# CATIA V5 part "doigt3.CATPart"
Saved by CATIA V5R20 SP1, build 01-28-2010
Part number: doigt3
Bounding box of the stored display mesh (mm): x -20 to -3, y -61.356 to 88.736, z -99.507 to -73.288
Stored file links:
  D:\thinkmotion-MPB\Dropbox\IAO_2011\MMS_GR1\0\IAO_2011_1470_mpeyrard\mpeyrard\mpeyrard\mpeyrard\IAO_2011_1470_mpeyrard\doigt3.CATPart
  D:\thinkmotion-MPB\Dropbox\IAO_2011\MMS_GR1\0\IAO_2011_1470_mpeyrard\mpeyrard\mpeyrard\mpeyrard\IAO_2011_1470_mpeyrard\mpeyrard.CATProduct
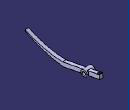
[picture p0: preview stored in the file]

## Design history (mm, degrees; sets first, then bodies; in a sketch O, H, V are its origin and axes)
External parameters (linked from other documents)
  External.Longueur_griffe = 70 mm
  External.Hauteur_griffe = 30 mm
Set1
  Line1: linked copy from another document
  Plane1: linked copy from another document
  Line2: linked copy from another document
  Line3: linked copy from another document
Body1 (main body)
  Sketch1 on yz-plane, origin (0, 0, 0), H (0, 1, 0), V (0, 0, 1)
    circle A1 centre (60, -86.6025) radius 3
    point P1 (60, -86.6025)
    circle A2 centre (60, -86.6025) radius 6
    reference projected point E1 (60, -86.6025) from Line1
    radius A2 = 6
    radius A1 = 3
    distance E1 P1 = 0
  Pad1: profile Sketch1, direction (-1, 0, 0), length 20, opposite side length -3
  Sketch2 on Plane1, origin (0, 54.6358, -87.6583), H (1, 0, 0), V (0, 0.9812, 0.1931)
    axis line L1 (-5.9206, 30.4671) -> (-26.1373, 30.4671)
    reference projected line E1 (0, 5.4671) -> (0, 30.4671) from Line2
    reference projected point E2 (0, 30.4671) from Line3
    line L2 (-13.5, 33.9671) -> (-6.5, 33.9671)
    line L3 (-6.5, 33.9671) -> (-6.5, -41.0329)
    line L4 (-6.5, -41.0329) -> (-13.5, -41.0329)
    line L5 (-13.5, -41.0329) -> (-13.5, 33.9671)
    reference projected point E3 (0, 30.4671) from Line3
    distance L1 E2 = 0
    distance L3 E3 = 6.5
    length L2 = 7
    distance L2 L1 = 3.5
    length L5 = 75
    perpendicularity: E1 L1
    horizontal: L2 H, L4 H
    vertical: L3 V, L5 V
  Pad2: profile Sketch2, direction (0, -0.1931, 0.9812), length 4, mirrored extent
  Sketch3 on start face of Pad2, origin (-9.7061, 81.2091, -86.5048), H (1, 0, 0), V (0, -0.9812, -0.1931)
    point P1 (-0.2939, -4.1713)
    reference projected line E1 (3.2061, -7.6713) -> (-3.7939, -7.6713) from edge [start face of Pad2 | face of Pad2 from Sketch2.L2]
    reference projected point E2 (9.7061, -4.1713) from Line3
    distance P1 E1 = 3.5
    distance P1 E2 = 10
  Hole1: placed by Sketch3, at (-10, 85.3019, -85.6993) direction (0, -0.1931, 0.9812), diameter 5, through (limit type 3)
  Sketch4 on face of Pad2 from Sketch2.L5, origin (-13.5, 0, 0), H (0, -1, 0), V (0, 0, 1)
    spline S1 through (-15.1478, -99.5073) (22.0901, -91.5488) (60.873, -75.7409)
    reference projected point E1 (-15.1478, -99.5073) from vertex [start face of Pad2 | face of Pad2 from Sketch2.L5 | face of Pad2 from Sketch2.L4]
    line L1 (-15.1478, -99.5073) -> (-13.6029, -91.6579)
    point P1 (-15.1478, -99.5073)
    point P2 (-13.6029, -91.6579)
    reference projected point E2 (-13.6029, -91.6579) from vertex [end face of Pad2 | face of Pad2 from Sketch2.L5 | face of Pad2 from Sketch2.L4]
    spline S2 through (61.3558, -73.288) (23.0557, -86.6429) (-13.6029, -91.6579)
    line L2 (60.873, -75.7409) -> (61.3558, -73.288)
    point P3 (60.873, -75.7409)
    point P4 (61.3558, -73.288)
    reference projected line E3 (-85.7702, -77.4536) -> (-12.182, -91.9375) from edge [face of Pad2 from Sketch2.L5 | end face of Pad2]
    reference projected line E4 (-90.1568, -84.7437) -> (-16.5687, -99.2276) from edge [start face of Pad2 | face of Pad2 from Sketch2.L5]
    point P5 (-15.1478, -99.5073)
    point P6 (61.3558, -73.288)
    point P7 (60.873, -75.7409)
    point P8 (-13.6029, -91.6579)
    point P9 (22.0901, -91.5488)
    point P10 (23.0557, -86.6429)
    length L2 = 2.5
    distance L1 L2 = 70 {= External.Longueur_griffe}
    distance E3 P3 = 30 {= External.Hauteur_griffe}
    distance P9 L1 = 35 {= External.Longueur_griffe/2}
    distance P10 L1 = 35 {= External.Longueur_griffe/2}
    distance P9 E4 = 15 {= External.Hauteur_griffe/2}
    distance P9 P10 = 5 {= 5mm}
    coincidence: P5 E1, P5 P1, P2 E2, P8 P2, P7 P3, P6 P4
  Pad3: profile Sketch4, direction (1, 0, 0), up to face of Pad2 from Sketch2.L3
  Sketch5 on face of Pad2 from Sketch2.L3, origin (-6.5, 59.3963, -86.4669), H (0, 1, 0), V (0, 0, 1)
    point P1 (0.6037, -0.1356)
    reference projected circle E1 centre (0.6037, -0.1356) radius 3 from edge [face of Pad1 from Sketch1.A1 | face of Pad2 from Sketch2.L3]
    concentricity: E1 P1
  Hole2: placed by Sketch5, at (-6.5, 60, -86.6025) direction (-1, 0, 0), diameter 6, through (limit type 3)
